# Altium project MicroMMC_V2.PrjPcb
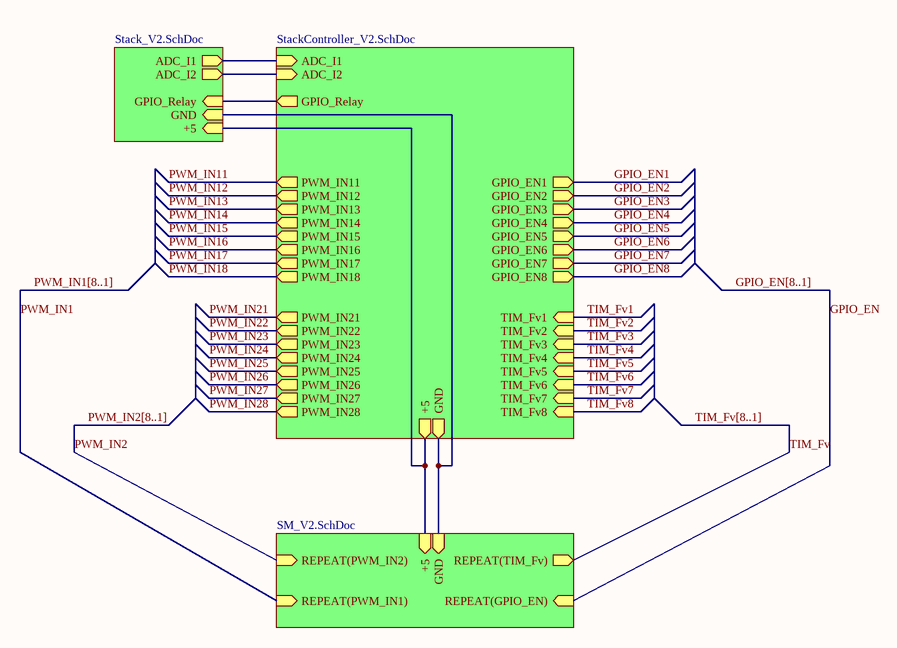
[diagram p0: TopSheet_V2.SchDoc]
4 sheets, 302 parts. Net scope: hierarchical (ports join the sheet entries above them; power ports are global).
Board file: MicroMMC_V2.PcbDoc
Sheets:
  TopSheet_V2.SchDoc
     = Stack_V2.SchDoc
     = StackController_V2.SchDoc
    1 = SM_V2.SchDoc
    2 = SM_V2.SchDoc
    3 = SM_V2.SchDoc
    4 = SM_V2.SchDoc
    5 = SM_V2.SchDoc
    6 = SM_V2.SchDoc
    7 = SM_V2.SchDoc
    8 = SM_V2.SchDoc

## Sheet TopSheet_V2.SchDoc
size A4

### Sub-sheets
REPEAT(,1,8) = SM_V2.SchDoc: REPEAT(PWM_IN1) (in), REPEAT(PWM_IN2) (in), REPEAT(GPIO_EN) (in), REPEAT(TIM_Fv) (out), GND (in), +5 (in)
? = Stack_V2.SchDoc: ADC_I1 (out), ADC_I2 (out), GPIO_Relay (in), GND (in), +5 (in)
? = StackController_V2.SchDoc: ADC_I1 (in), GPIO_Relay (out), PWM_IN11 (out), PWM_IN21 (out), GPIO_EN1 (out), ADC_I2 (in), TIM_Fv1 (in), GPIO_EN2 (out), GPIO_EN3 (out), GPIO_EN4 (out), GPIO_EN5 (out), GPIO_EN6 (out), GPIO_EN7 (out), GPIO_EN8 (out), TIM_Fv2 (in), TIM_Fv3 (in), TIM_Fv4 (in), TIM_Fv5 (in), TIM_Fv6 (in), TIM_Fv7 (in), TIM_Fv8 (in), PWM_IN12 (out), PWM_IN13 (out), PWM_IN14 (out), PWM_IN15 (out), PWM_IN16 (out), PWM_IN17 (out), PWM_IN18 (out), PWM_IN22 (out), PWM_IN23 (out), PWM_IN24 (out), PWM_IN25 (out), PWM_IN26 (out), PWM_IN27 (out), PWM_IN28 (out), +5 (out), GND (out)

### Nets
+5: sheet /+5, sheet /+5, sheet REPEAT(,1,8)/+5
GND: sheet /GND, sheet /GND, sheet REPEAT(,1,8)/GND
ADC_I1: sheet /ADC_I1, sheet /ADC_I1
ADC_I2: sheet /ADC_I2, sheet /ADC_I2
GPIO_Relay: sheet /GPIO_Relay, sheet /GPIO_Relay

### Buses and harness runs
bus GPIO_EN[8..1]
bus PWM_IN1[8..1]
bus PWM_IN2[8..1]
bus TIM_Fv[8..1]

## Sheet Stack_V2.SchDoc
size A4
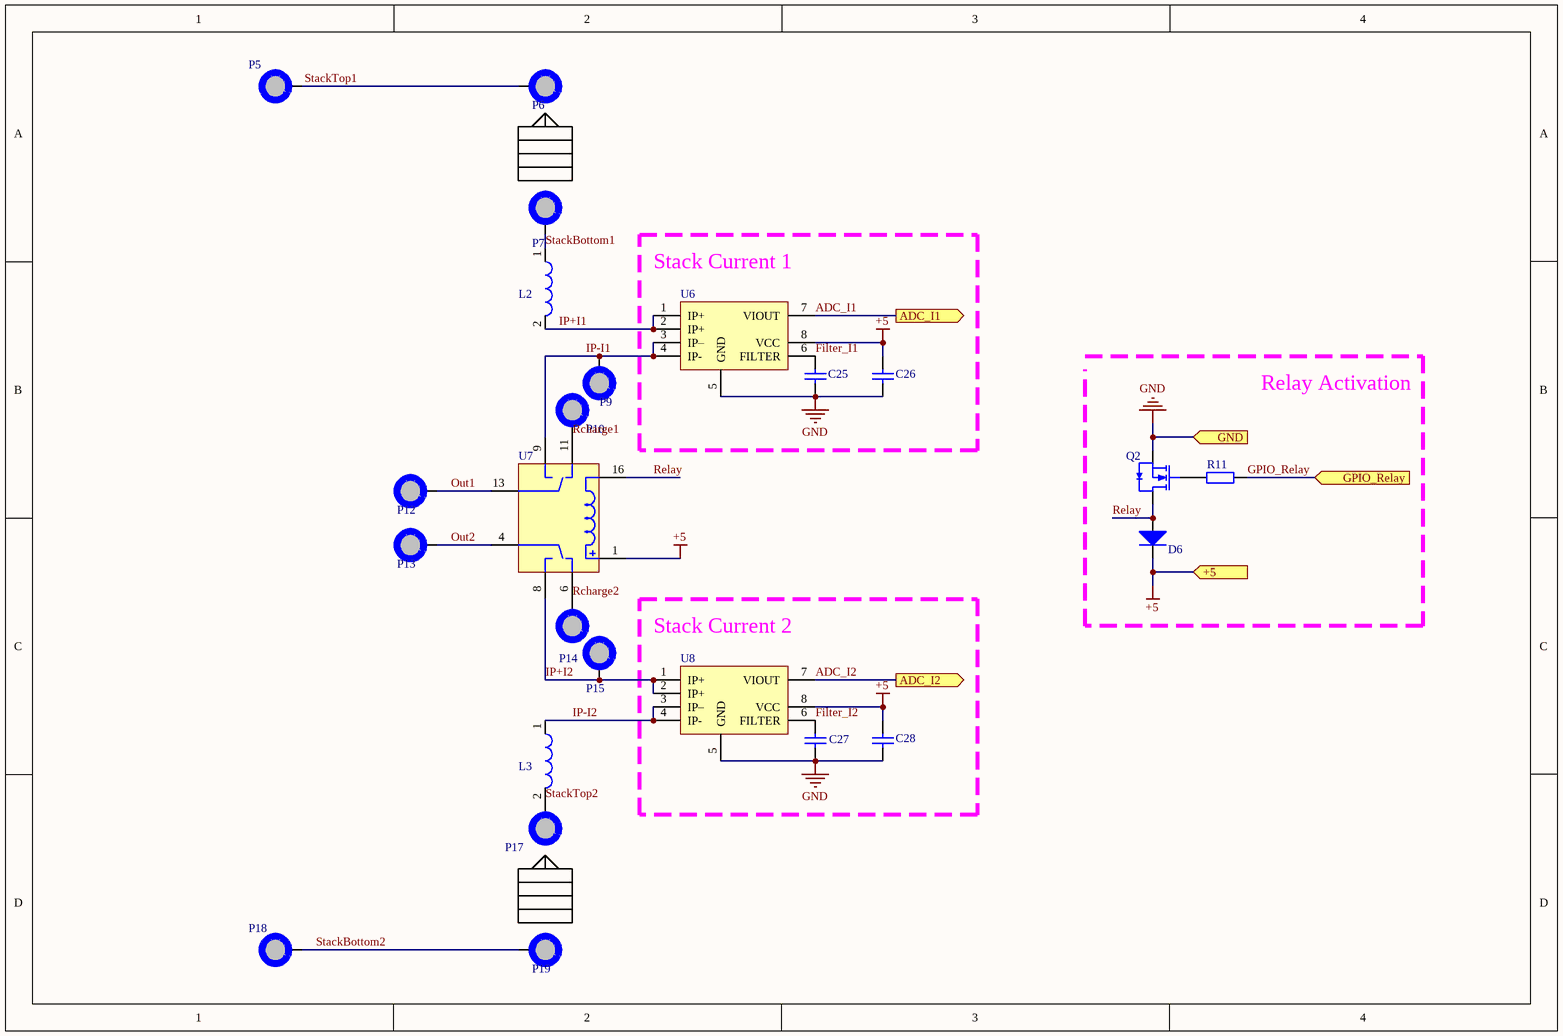
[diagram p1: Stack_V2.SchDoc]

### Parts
C25  1nF (102) ±10% 50V X7R  [0402_C]  (value not drawn)
C26  100nF (104) ±10% 16V X7R  [0402_C]  (value not drawn)
C27  1nF (102) ±10% 50V X7R  [0402_C]  (value not drawn)
C28  100nF (104) ±10% 16V X7R  [0402_C]  (value not drawn)
D6  B5819W  [SOD-123]  (value not drawn)
L2  1140-122K-RC  [INDRD2921W163D3810H2616P]  (value not drawn)
L3  1140-122K-RC  [INDRD2921W163D3810H2616P]  (value not drawn)
P5  4MMx1MM5  [Pad with hole]  (value not drawn)
P6  4MMx1MM5  [Pad with hole]  (value not drawn)
P7  4MMx1MM5  [Pad with hole]  (value not drawn)
P9  4MMx1MM5  [Pad with hole]  (value not drawn)
P10  4MMx1MM5  [Pad with hole]  (value not drawn)
P12  4MMx1MM5  [Pad with hole]  (value not drawn)
P13  4MMx1MM5  [Pad with hole]  (value not drawn)
P14  4MMx1MM5  [Pad with hole]  (value not drawn)
P15  4MMx1MM5  [Pad with hole]  (value not drawn)
P17  4MMx1MM5  [Pad with hole]  (value not drawn)
P18  4MMx1MM5  [Pad with hole]  (value not drawn)
P19  4MMx1MM5  [Pad with hole]  (value not drawn)
Q2  2N7002  [SOT-23(SOT-23-3)]  (value not drawn)
R11  1KΩ (1001) ±1%  [0402_R]  (value not drawn)
U6  ACS712ELCTR-05B-T  [SOIC-8_150mil]  (value not drawn)
U7  V23105A5001A201  [Relay_V23105A5001A201]  (value not drawn)
U8  ACS712ELCTR-05B-T  [SOIC-8_150mil]  (value not drawn)

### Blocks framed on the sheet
Stack Current 1: C25 C26 U6
Stack Current 2: C27 C28 U8

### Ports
+5 (in), ADC_I1 (out), ADC_I2 (out), GND (in), GPIO_Relay (in)

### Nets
+5: C26.2 C28.2 D6.2(K) U6.8(VCC) U7.1 U8.8(VCC) ; port +5
GND: C25.1 C26.1 C27.1 C28.1 Q2.2(S) U6.5(GND) U8.5(GND) ; port GND
ADC_I1: U6.7(VIOUT) ; port ADC_I1
ADC_I2: U8.7(VIOUT) ; port ADC_I2
Filter_I1: C25.2 U6.6(FILTER)
Filter_I2: C27.2 U8.6(FILTER)
GPIO_Relay: R11.1 ; port GPIO_Relay
IP+I1: L2.2 U6.1(IP+) U6.2(IP+)
IP+I2: P15.1 U7.8 U8.1(IP+) U8.2(IP+)
IP-I1: P9.1 U6.3(IP–) U6.4(IP-) U7.9
IP-I2: L3.1 U8.3(IP–) U8.4(IP-)
Out1: P12.1 U7.13
Out2: P13.1 U7.4
Rcharge1: P10.1 U7.11
Rcharge2: P14.1 U7.6
Relay: D6.1(A) Q2.3(D) U7.16
StackBottom1: L2.1 P7.1
StackBottom2: P18.1 P19.1
StackTop1: P5.1 P6.1
StackTop2: L3.2 P17.1
NetQ2_1: Q2.1(G) R11.2

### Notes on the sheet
- Relay Activation

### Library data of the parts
C25 C27 = 1nF (102) ±10% 50V X7R: C1523 贴片电容 0402
C26 C28 = 100nF (104) ±10% 16V X7R: C1525 贴片电容 0402
D6 = B5819W: C8598 SOD-123
L2 L3 = 1140-122K-RC: C1329703 Radial; MF: Bourns
P5-P7 P9 P10 P12-P15 P17-P19 = PAD_WITH_HOLE_4MMx1MM5
Q2 = 2N7002: C8545 SOT-23-3
R11 = 1KΩ (1001) ±1%: C11702 贴片电阻 0402
U6 U8 = ACS712ELCTR-05B-T: C44471 电流传感器 SOIC-8_3.9X4.9X1.27P
U7 = V23105A5001A201: 3A 5V; Manufacturer: TE Connectivity Axicom; Throw Configuration: DPDT; Coil Resistance: 167R; Coil Current: 29.76mA; Max Voltage Rating (AC): 250V; Max Voltage Rating (DC): 220V; Coil Type: Non-Latching; Coil Power: 150mW; Relay Type: Relay; Actuating System: AC/DC; Insertion Loss: -0.27dB; Ratings: IP67; Approvals: cULus

## Sheet StackController_V2.SchDoc
size A3
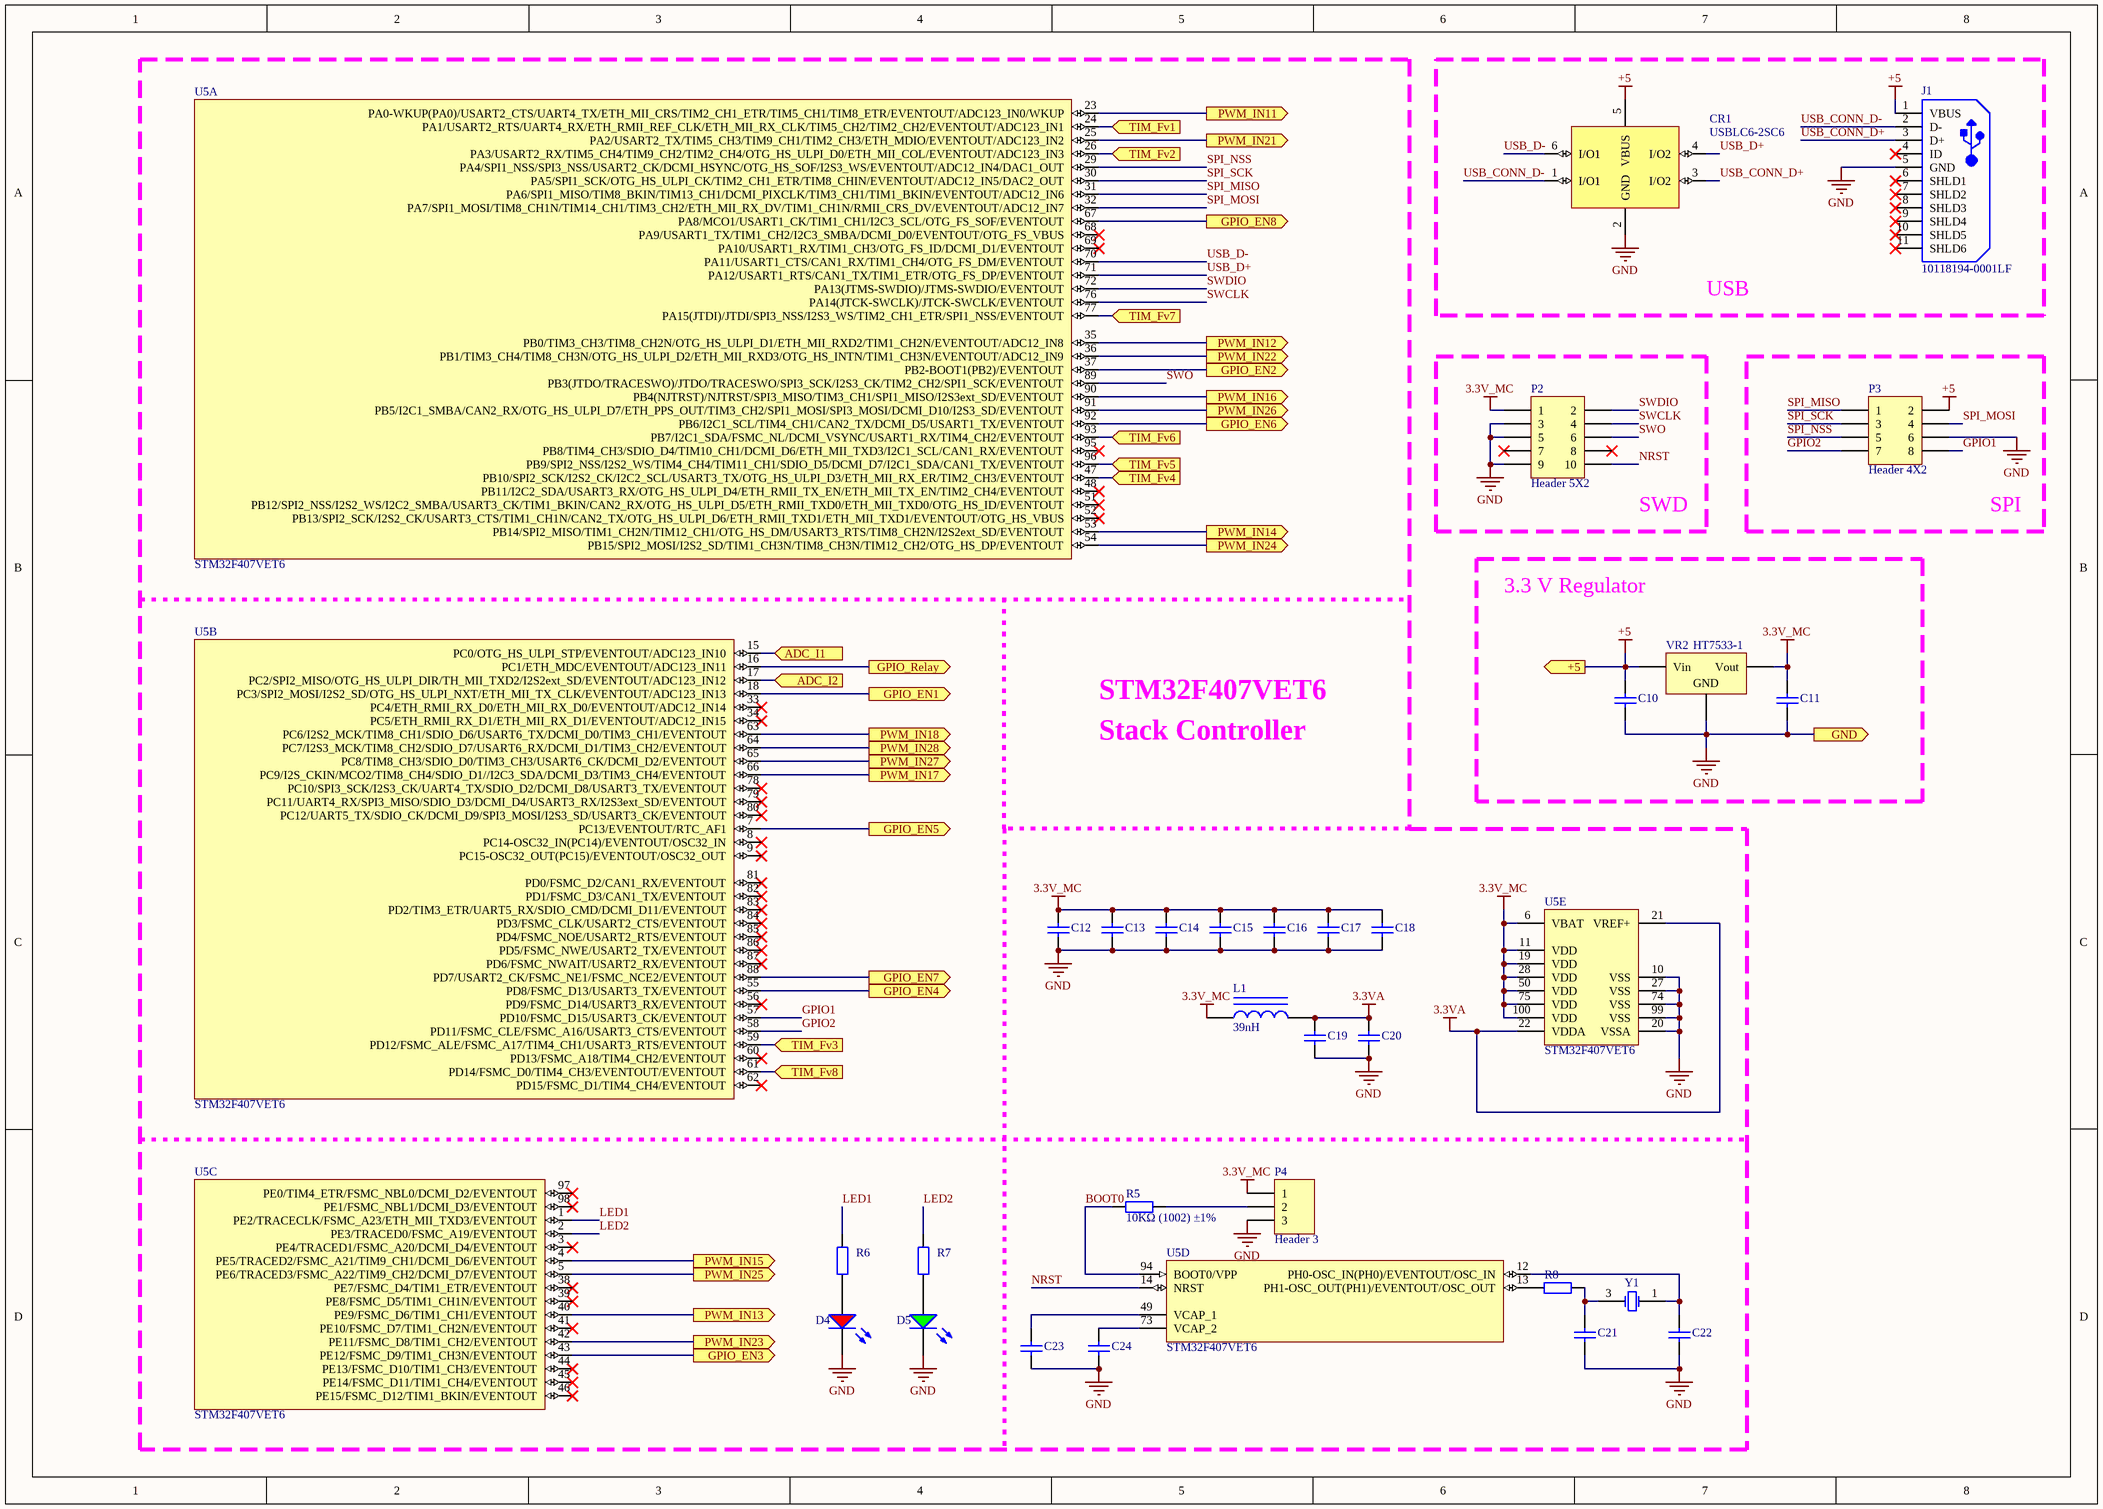
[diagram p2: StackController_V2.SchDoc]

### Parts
C10  10uF (106) ±20% 6.3V X5R  [0402_C]  (value not drawn)
C11  10uF (106) ±20% 6.3V X5R  [0402_C]  (value not drawn)
C12  4.7uF (475) ±20% 10V X5R  [0402_C]  (value not drawn)
C13  100nF (104) ±10% 16V X7R  [0402_C]  (value not drawn)
C14  100nF (104) ±10% 16V X7R  [0402_C]  (value not drawn)
C15  100nF (104) ±10% 16V X7R  [0402_C]  (value not drawn)
C16  100nF (104) ±10% 16V X7R  [0402_C]  (value not drawn)
C17  100nF (104) ±10% 16V X7R  [0402_C]  (value not drawn)
C18  100nF (104) ±10% 16V X7R  [0402_C]  (value not drawn)
C19  1uF (105) ±10% 25V X5R  [0402_C]  (value not drawn)
C20  100nF (104) ±10% 16V X7R  [0402_C]  (value not drawn)
C21  12pF (120) ±5% 50V C0G  [0402_C]  (value not drawn)
C22  12pF (120) ±5% 50V C0G  [0402_C]  (value not drawn)
C23  2.2uF (225) ±10% 16V X5R  [0603_C]  (value not drawn)
C24  2.2uF (225) ±10% 16V X5R  [0603_C]  (value not drawn)
CR1  USBLC6-2SC6  [SOT23-6L_STM]
D4  LED_灯_红_Iv=100-120_λd=615-630  [0603_LED_S1]  (value not drawn)
D5  LED_灯_绿_Iv=112-285_λd=520-535  [0603_LED_S1]  (value not drawn)
J1  10118194-0001LF  [FCI-10118194-0001LF-5_V]
L1  39nH  [0402_L]
P2  Header 5X2  [HDR2.54-LI-2x5P]
P3  Header 4X2  [HDR2.54-LI-2x4P]
P4  Header 3  [HDR2.54-LI-3P]
R5  10KΩ (1002) ±1%  [0402_R]
R6  2.4KΩ (2401) ±1%  [0402_R]  (value not drawn)
R7  2.4KΩ (2401) ±1%  [0402_R]  (value not drawn)
R8  47Ω (47R0) ±1%  [0402_R]  (value not drawn)
U5  STM32F407VET6  [LQFP-100_14x14x05P]  (parts A,B,C,D,E of 5)
VR2  HT7533-1  [SOT-89(SOT-89-3)]
Y1  16MHZ 9PF 10PPM  [SMD-3225_4P]  (value not drawn)

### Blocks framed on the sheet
USB: CR1 J1
SWD: P2
SPI: P3
3.3 V Regulator: C10 C11 VR2

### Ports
+5 (out), ADC_I1 (in), ADC_I2 (in), GND (out), GPIO_EN1 (out), GPIO_EN2 (out), GPIO_EN3 (out), GPIO_EN4 (out), GPIO_EN5 (out), GPIO_EN6 (out), GPIO_EN7 (out), GPIO_EN8 (out), GPIO_Relay (out), PWM_IN11 (out), PWM_IN12 (out), PWM_IN13 (out), PWM_IN14 (out), PWM_IN15 (out), PWM_IN16 (out), PWM_IN17 (out), PWM_IN18 (out), PWM_IN21 (out), PWM_IN22 (out), PWM_IN23 (out), PWM_IN24 (out), PWM_IN25 (out), PWM_IN26 (out), PWM_IN27 (out), PWM_IN28 (out), TIM_Fv1 (in), TIM_Fv2 (in), TIM_Fv3 (in), TIM_Fv4 (in), TIM_Fv5 (in), TIM_Fv6 (in), TIM_Fv7 (in), TIM_Fv8 (in)

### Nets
3.3V_MC: C11.2 C12.2 C13.2 C14.2 C15.2 C16.2 C17.2 C18.2 L1.1 P2.1 P4.1 U5.6(VBAT) U5.11(VDD) U5.19(VDD) U5.28(VDD) U5.50(VDD) U5.75(VDD) U5.100(VDD) VR2.3(Vout)
3.3VA: C19.1 C20.2 L1.2 U5.21(VREF+) U5.22(VDDA)
+5: C10.2 CR1.5(VBUS) J1.1(VBUS) P3.2 VR2.2(Vin) ; port +5
GND: C10.1 C11.1 C12.1 C13.1 C14.1 C15.1 C16.1 C17.1 C18.1 C19.2 C20.1 C21.1 C22.1 C23.1 C24.1 CR1.2(GND) D4.K D5.K J1.5(GND) P2.3 P2.5 P2.9 P3.6 P4.3 U5.10(VSS) U5.20(VSSA) U5.27(VSS) U5.74(VSS) U5.99(VSS) VR2.1(GND) ; port GND
ADC_I1: U5.15(PC0/OTG_HS_ULPI_STP/EVENTOUT/ADC123_IN10) ; port ADC_I1
ADC_I2: U5.17(PC2/SPI2_MISO/OTG_HS_ULPI_DIR/TH_MII_TXD2/I2S2ext_SD/EVENTOUT/ADC123_IN12) ; port ADC_I2
BOOT0: R5.1 U5.94(BOOT0/VPP)
GPIO1: P3.8 U5.57(PD10/FSMC_D15/USART3_CK/EVENTOUT)
GPIO2: P3.7 U5.58(PD11/FSMC_CLE/FSMC_A16/USART3_CTS/EVENTOUT)
GPIO_EN1: U5.18(PC3/SPI2_MOSI/I2S2_SD/OTG_HS_ULPI_NXT/ETH_MII_TX_CLK/EVENTOUT/ADC123_IN13) ; port GPIO_EN1
GPIO_EN2: U5.37(PB2-BOOT1(PB2)/EVENTOUT) ; port GPIO_EN2
GPIO_EN3: U5.43(PE12/FSMC_D9/TIM1_CH3N/EVENTOUT) ; port GPIO_EN3
GPIO_EN4: U5.55(PD8/FSMC_D13/USART3_TX/EVENTOUT) ; port GPIO_EN4
GPIO_EN5: U5.7(PC13/EVENTOUT/RTC_AF1) ; port GPIO_EN5
GPIO_EN6: U5.92(PB6/I2C1_SCL/TIM4_CH1/CAN2_TX/DCMI_D5/USART1_TX/EVENTOUT) ; port GPIO_EN6
GPIO_EN7: U5.88(PD7/USART2_CK/FSMC_NE1/FSMC_NCE2/EVENTOUT) ; port GPIO_EN7
GPIO_EN8: U5.67(PA8/MCO1/USART1_CK/TIM1_CH1/I2C3_SCL/OTG_FS_SOF/EVENTOUT) ; port GPIO_EN8
GPIO_Relay: U5.16(PC1/ETH_MDC/EVENTOUT/ADC123_IN11) ; port GPIO_Relay
LED1: R6.2 U5.1(PE2/TRACECLK/FSMC_A23/ETH_MII_TXD3/EVENTOUT)
LED2: R7.2 U5.2(PE3/TRACED0/FSMC_A19/EVENTOUT)
NRST: P2.10 U5.14(NRST)
PWM_IN11: U5.23(PA0-WKUP(PA0)/USART2_CTS/UART4_TX/ETH_MII_CRS/TIM2_CH1_ETR/TIM5_CH1/TIM8_ETR/EVENTOUT/ADC123_IN0/WKUP) ; port PWM_IN11
PWM_IN12: U5.35(PB0/TIM3_CH3/TIM8_CH2N/OTG_HS_ULPI_D1/ETH_MII_RXD2/TIM1_CH2N/EVENTOUT/ADC12_IN8) ; port PWM_IN12
PWM_IN13: U5.40(PE9/FSMC_D6/TIM1_CH1/EVENTOUT) ; port PWM_IN13
PWM_IN14: U5.53(PB14/SPI2_MISO/TIM1_CH2N/TIM12_CH1/OTG_HS_DM/USART3_RTS/TIM8_CH2N/I2S2ext_SD/EVENTOUT) ; port PWM_IN14
PWM_IN15: U5.4(PE5/TRACED2/FSMC_A21/TIM9_CH1/DCMI_D6/EVENTOUT) ; port PWM_IN15
PWM_IN16: U5.90(PB4(NJTRST)/NJTRST/SPI3_MISO/TIM3_CH1/SPI1_MISO/I2S3ext_SD/EVENTOUT) ; port PWM_IN16
PWM_IN17: U5.66(PC9/I2S_CKIN/MCO2/TIM8_CH4/SDIO_D1//I2C3_SDA/DCMI_D3/TIM3_CH4/EVENTOUT) ; port PWM_IN17
PWM_IN18: U5.63(PC6/I2S2_MCK/TIM8_CH1/SDIO_D6/USART6_TX/DCMI_D0/TIM3_CH1/EVENTOUT) ; port PWM_IN18
PWM_IN21: U5.25(PA2/USART2_TX/TIM5_CH3/TIM9_CH1/TIM2_CH3/ETH_MDIO/EVENTOUT/ADC123_IN2) ; port PWM_IN21
PWM_IN22: U5.36(PB1/TIM3_CH4/TIM8_CH3N/OTG_HS_ULPI_D2/ETH_MII_RXD3/OTG_HS_INTN/TIM1_CH3N/EVENTOUT/ADC12_IN9) ; port PWM_IN22
PWM_IN23: U5.42(PE11/FSMC_D8/TIM1_CH2/EVENTOUT) ; port PWM_IN23
PWM_IN24: U5.54(PB15/SPI2_MOSI/I2S2_SD/TIM1_CH3N/TIM8_CH3N/TIM12_CH2/OTG_HS_DP/EVENTOUT) ; port PWM_IN24
PWM_IN25: U5.5(PE6/TRACED3/FSMC_A22/TIM9_CH2/DCMI_D7/EVENTOUT) ; port PWM_IN25
PWM_IN26: U5.91(PB5/I2C1_SMBA/CAN2_RX/OTG_HS_ULPI_D7/ETH_PPS_OUT/TIM3_CH2/SPI1_MOSI/SPI3_MOSI/DCMI_D10/I2S3_SD/EVENTOUT) ; port PWM_IN26
PWM_IN27: U5.65(PC8/TIM8_CH3/SDIO_D0/TIM3_CH3/USART6_CK/DCMI_D2/EVENTOUT) ; port PWM_IN27
PWM_IN28: U5.64(PC7/I2S3_MCK/TIM8_CH2/SDIO_D7/USART6_RX/DCMI_D1/TIM3_CH2/EVENTOUT) ; port PWM_IN28
SPI_MISO: P3.1 U5.31(PA6/SPI1_MISO/TIM8_BKIN/TIM13_CH1/DCMI_PIXCLK/TIM3_CH1/TIM1_BKIN/EVENTOUT/ADC12_IN6)
SPI_MOSI: P3.4 U5.32(PA7/SPI1_MOSI/TIM8_CH1N/TIM14_CH1/TIM3_CH2/ETH_MII_RX_DV/TIM1_CH1N/RMII_CRS_DV/EVENTOUT/ADC12_IN7)
SPI_NSS: P3.5 U5.29(PA4/SPI1_NSS/SPI3_NSS/USART2_CK/DCMI_HSYNC/OTG_HS_SOF/I2S3_WS/EVENTOUT/ADC12_IN4/DAC1_OUT)
SPI_SCK: P3.3 U5.30(PA5/SPI1_SCK/OTG_HS_ULPI_CK/TIM2_CH1_ETR/TIM8_CHIN/EVENTOUT/ADC12_IN5/DAC2_OUT)
SWCLK: P2.4 U5.76(PA14(JTCK-SWCLK)/JTCK-SWCLK/EVENTOUT)
SWDIO: P2.2 U5.72(PA13(JTMS-SWDIO)/JTMS-SWDIO/EVENTOUT)
SWO: P2.6 U5.89(PB3(JTDO/TRACESWO)/JTDO/TRACESWO/SPI3_SCK/I2S3_CK/TIM2_CH2/SPI1_SCK/EVENTOUT)
TIM_Fv1: U5.24(PA1/USART2_RTS/UART4_RX/ETH_RMII_REF_CLK/ETH_MII_RX_CLK/TIM5_CH2/TIM2_CH2/EVENTOUT/ADC123_IN1) ; port TIM_Fv1
TIM_Fv2: U5.26(PA3/USART2_RX/TIM5_CH4/TIM9_CH2/TIM2_CH4/OTG_HS_ULPI_D0/ETH_MII_COL/EVENTOUT/ADC123_IN3) ; port TIM_Fv2
TIM_Fv3: U5.59(PD12/FSMC_ALE/FSMC_A17/TIM4_CH1/USART3_RTS/EVENTOUT) ; port TIM_Fv3
TIM_Fv4: U5.47(PB10/SPI2_SCK/I2S2_CK/I2C2_SCL/USART3_TX/OTG_HS_ULPI_D3/ETH_MII_RX_ER/TIM2_CH3/EVENTOUT) ; port TIM_Fv4
TIM_Fv5: U5.96(PB9/SPI2_NSS/I2S2_WS/TIM4_CH4/TIM11_CH1/SDIO_D5/DCMI_D7/I2C1_SDA/CAN1_TX/EVENTOUT) ; port TIM_Fv5
TIM_Fv6: U5.93(PB7/I2C1_SDA/FSMC_NL/DCMI_VSYNC/USART1_RX/TIM4_CH2/EVENTOUT) ; port TIM_Fv6
TIM_Fv7: U5.77(PA15(JTDI)/JTDI/SPI3_NSS/I2S3_WS/TIM2_CH1_ETR/SPI1_NSS/EVENTOUT) ; port TIM_Fv7
TIM_Fv8: U5.61(PD14/FSMC_D0/TIM4_CH3/EVENTOUT/EVENTOUT) ; port TIM_Fv8
USB_CONN_D+: CR1.3(I/O2) J1.3(D+)
USB_CONN_D-: CR1.1(I/O1) J1.2(D-)
USB_D+: CR1.4(I/O2) U5.71(PA12/USART1_RTS/CAN1_TX/TIM1_ETR/OTG_FS_DP/EVENTOUT)
USB_D-: CR1.6(I/O1) U5.70(PA11/USART1_CTS/CAN1_RX/TIM1_CH4/OTG_FS_DM/EVENTOUT)
NetC21_2: C21.2 R8.2 Y1.3(OSC2)
NetC22_2: C22.2 U5.12(PH0-OSC_IN(PH0)/EVENTOUT/OSC_IN) Y1.1(OSC1)
NetC23_2: C23.2 U5.49(VCAP_1)
NetC24_2: C24.2 U5.73(VCAP_2)
NetD4_A: D4.A R6.1
NetD5_A: D5.A R7.1
NetP4_2: P4.2 R5.2
NetR8_1: R8.1 U5.13(PH1-OSC_OUT(PH1)/EVENTOUT/OSC_OUT)

Not connected (* = marked no-connect by the designer): J1 4(ID)* 6(SHLD1)* 7(SHLD2)* 8(SHLD3)* 9(SHLD4)* 10(SHLD5)* 11(SHLD6)*; P2 7* 8*; U5 3(PE4/TRACED1/FSMC_A20/DCMI_D4/EVENTOUT)* 8(PC14-OSC32_IN(PC14)/EVENTOUT/OSC32_IN)* 9(PC15-OSC32_OUT(PC15)/EVENTOUT/OSC32_OUT)* 33(PC4/ETH_RMII_RX_D0/ETH_MII_RX_D0/EVENTOUT/ADC12_IN14)* 34(PC5/ETH_RMII_RX_D1/ETH_MII_RX_D1/EVENTOUT/ADC12_IN15)* 38(PE7/FSMC_D4/TIM1_ETR/EVENTOUT)* 39(PE8/FSMC_D5/TIM1_CH1N/EVENTOUT)* 41(PE10/FSMC_D7/TIM1_CH2N/EVENTOUT)* 44(PE13/FSMC_D10/TIM1_CH3/EVENTOUT)* 45(PE14/FSMC_D11/TIM1_CH4/EVENTOUT)* 46(PE15/FSMC_D12/TIM1_BKIN/EVENTOUT)* 48(PB11/I2C2_SDA/USART3_RX/OTG_HS_ULPI_D4/ETH_RMII_TX_EN/ETH_MII_TX_EN/TIM2_CH4/EVENTOUT)* 51(PB12/SPI2_NSS/I2S2_WS/I2C2_SMBA/USART3_CK/TIM1_BKIN/CAN2_RX/OTG_HS_ULPI_D5/ETH_RMII_TXD0/ETH_MII_TXD0/OTG_HS_ID/EVENTOUT)* 52(PB13/SPI2_SCK/I2S2_CK/USART3_CTS/TIM1_CH1N/CAN2_TX/OTG_HS_ULPI_D6/ETH_RMII_TXD1/ETH_MII_TXD1/EVENTOUT/OTG_HS_VBUS)* 56(PD9/FSMC_D14/USART3_RX/EVENTOUT)* 60(PD13/FSMC_A18/TIM4_CH2/EVENTOUT)* 62(PD15/FSMC_D1/TIM4_CH4/EVENTOUT)* 68(PA9/USART1_TX/TIM1_CH2/I2C3_SMBA/DCMI_D0/EVENTOUT/OTG_FS_VBUS)* 69(PA10/USART1_RX/TIM1_CH3/OTG_FS_ID/DCMI_D1/EVENTOUT)* 78(PC10/SPI3_SCK/I2S3_CK/UART4_TX/SDIO_D2/DCMI_D8/USART3_TX/EVENTOUT)* 79(PC11/UART4_RX/SPI3_MISO/SDIO_D3/DCMI_D4/USART3_RX/I2S3ext_SD/EVENTOUT)* 80(PC12/UART5_TX/SDIO_CK/DCMI_D9/SPI3_MOSI/I2S3_SD/USART3_CK/EVENTOUT)* 81(PD0/FSMC_D2/CAN1_RX/EVENTOUT)* 82(PD1/FSMC_D3/CAN1_TX/EVENTOUT)* 83(PD2/TIM3_ETR/UART5_RX/SDIO_CMD/DCMI_D11/EVENTOUT)* 84(PD3/FSMC_CLK/USART2_CTS/EVENTOUT)* 85(PD4/FSMC_NOE/USART2_RTS/EVENTOUT)* 86(PD5/FSMC_NWE/USART2_TX/EVENTOUT)* 87(PD6/FSMC_NWAIT/USART2_RX/EVENTOUT)* 95(PB8/TIM4_CH3/SDIO_D4/TIM10_CH1/DCMI_D6/ETH_MII_TXD3/I2C1_SCL/CAN1_RX/EVENTOUT)* 97(PE0/TIM4_ETR/FSMC_NBL0/DCMI_D2/EVENTOUT)* 98(PE1/FSMC_NBL1/DCMI_D3/EVENTOUT)*

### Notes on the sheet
- STM32F407VET6
- Stack Controller

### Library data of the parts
C10 C11 = 10uF (106) ±20% 6.3V X5R: C15525 贴片电容 0402
C12 = 4.7uF (475) ±20% 10V X5R: C23733 贴片电容 0402
C13-C18 C20 = 100nF (104) ±10% 16V X7R: C1525 贴片电容 0402
C19 = 1uF (105) ±10% 25V X5R: C52923 贴片电容 0402
C21 C22 = 12pF (120) ±5% 50V C0G: C1547 贴片电容 0402
C23 C24 = 2.2uF (225) ±10% 16V X5R: C23630 贴片电容 0603
CR1 = USBLC6-2SC6: C7519 SOT-23-6L; Built_By: EMA_UL_Team; Vendor: STMicroelectronics; SourceLibrary: Update_database_2020-10-15; Type: DEV
D4 = LED_灯_红_Iv=100-120_λd=615-630: C2286 发光二极管 LED_0603
D5 = LED_灯_绿_Iv=112-285_λd=520-535: C72043 发光二极管 LED_0603
J1 = 10118194-0001LF: C132563; Manufacturer: Amphenol FCI; Body Orientation: RightAngle; Number of Contacts: 5; Pitch: 0.65mm; Gender: RCP; Rad Hard: No
L1 = 39nH: C26443 贴片电感 0402
P2 = Header 5X2: C124387
P3 = Header 4X2: C124386
P4 = Header 3: C124376
R5 = 10KΩ (1002) ±1%: C25744 贴片电阻 0402
R6 R7 = 2.4KΩ (2401) ±1%: C25882 贴片电阻 0402
R8 = 47Ω (47R0) ±1%: C25118 贴片电阻 0402
U5 = STM32F407VET6: C28730 ARM
VR2 = HT7533-1: C14289 低压差线性稳压(LDO) SOT-89
Y1 = 16MHZ 9PF 10PPM: C13738 贴片晶振

## Sheet SM_V2.SchDoc
size A4
Used 8 times, as channels 1, 2, 3, 4, 5, 6, 7, 8. Parts and nets are listed once, with the designators drawn on the sheet.
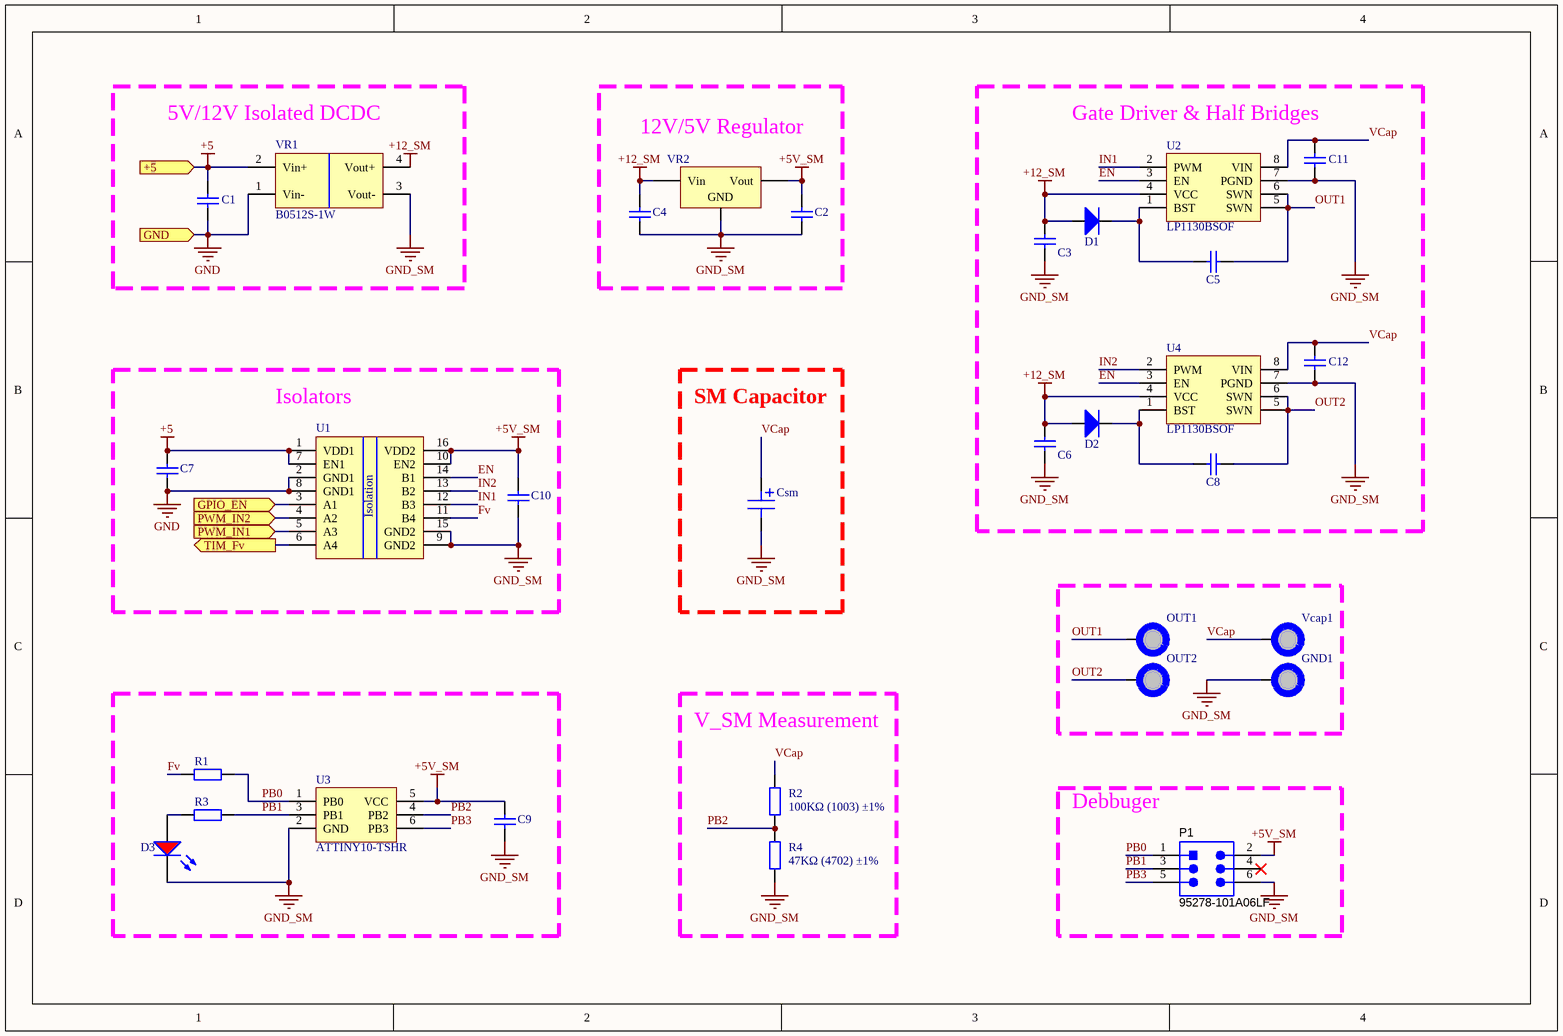
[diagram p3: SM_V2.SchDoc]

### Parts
C1  10uF (106) ±20% 6.3V X5R  [0402_C]  (value not drawn)
C2  10uF (106) ±20% 6.3V X5R  [0402_C]  (value not drawn)
C3  1uF (105) ±10% 25V X5R  [0402_C]  (value not drawn)
C4  10uF 16V  [0603_C]  (value not drawn)
C5  1uF (105) ±10% 25V X5R  [0402_C]  (value not drawn)
C6  1uF (105) ±10% 25V X5R  [0402_C]  (value not drawn)
C7  100nF (104) ±10% 16V X7R  [0402_C]  (value not drawn)
C8  1uF (105) ±10% 25V X5R  [0402_C]  (value not drawn)
C9  100nF (104) ±10% 16V X7R  [0402_C]  (value not drawn)
C10  100nF (104) ±10% 16V X7R  [0402_C]  (value not drawn)
C11  1uF (105) ±10% 25V X5R  [0402_C]  (value not drawn)
C12  1uF (105) ±10% 25V X5R  [0402_C]  (value not drawn)
Csm  6800uF 16V  [6800uF 16V 16*25]  (value not drawn)
D1  B5819W  [SOD-123]  (value not drawn)
D2  B5819W  [SOD-123]  (value not drawn)
D3  LED_灯_红_Iv=100-120_λd=615-630  [0603_LED_S1]  (value not drawn)
GND1  4MMx1MM5  [Pad with hole]  (value not drawn)
OUT1  4MMx1MM5  [Pad with hole]  (value not drawn)
OUT2  4MMx1MM5  [Pad with hole]  (value not drawn)
P1  95278-101A06LF  [AMPM-95278-101A06LF_V]
R1  1KΩ (1001) ±1%  [0402_R]  (value not drawn)
R2  100KΩ (1003) ±1%  [0402_R]
R3  2.4KΩ (2401) ±1%  [0402_R]  (value not drawn)
R4  47KΩ (4702) ±1%  [0402_R]
U1  SI8641BD-B-ISR  [SOIC-16W_SIL]  (value not drawn)
U2  LP1130BSOF  [SOP_8_LP1130B]
U3  ATTINY10-TSHR  [6ST1_ATM]
U4  LP1130BSOF  [SOP_8_LP1130B]
Vcap1  4MMx1MM5  [Pad with hole]  (value not drawn)
VR1  B0512S-1W  [B0512S-1W]
VR2  78L05G-AB3-R  [SOT-89(SOT-89-3)]  (value not drawn)

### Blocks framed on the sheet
5V/12V Isolated DCDC: C1 VR1
12V/5V Regulator: C2 C4 VR2
Gate Driver & Half Bridges: C3 C5 C6 C8 C11 C12 D1 D2 U2 U4
Isolators: C7 C10 U1
SM Capacitor: Csm
V_SM Measurement: R2 R4
Debbuger: P1

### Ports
+5 (in), GND (in), GPIO_EN (in), PWM_IN1 (in), PWM_IN2 (in), TIM_Fv (out)

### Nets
+5: C1.2 C7.2 U1.1(VDD1) U1.7(EN1) VR1.2(Vin+) ; port +5
+5V_SM: C2.2 C9.2 C10.2 P1.2 U1.10(EN2) U1.16(VDD2) U3.5(VCC) VR2.1(Vout)
+12_SM: C3.2 C4.2 C6.2 D1.1(A) D2.1(A) U2.4(VCC) U4.4(VCC) VR1.4(Vout+) VR2.3(Vin)
GND: C1.1 C7.1 U1.2(GND1) U1.8(GND1) VR1.1(Vin-) ; port GND
GND_SM: C2.1 C3.1 C4.1 C6.1 C9.1 C10.1 C11.1 C12.1 Csm.2 D3.K GND1.1 P1.6 R4.1 U1.9(GND2) U1.15(GND2) U2.7(PGND) U3.2(GND) U4.7(PGND) VR1.3(Vout-) VR2.2(GND)
EN: U1.14(B1) U2.3(EN) U4.3(EN)
Fv: R1.1 U1.11(B4)
GPIO_EN: U1.3(A1) ; port GPIO_EN
IN1: U1.12(B3) U2.2(PWM)
IN2: U1.13(B2) U4.2(PWM)
OUT1: C5.2 OUT1.1 U2.5(SWN) U2.6(SWN)
OUT2: C8.2 OUT2.1 U4.5(SWN) U4.6(SWN)
PB0: P1.1 R1.2 U3.1(PB0)
PB1: P1.3 R3.2 U3.3(PB1)
PB2: R2.1 R4.2 U3.4(PB2)
PB3: P1.5 U3.6(PB3)
PWM_IN1: U1.5(A3) ; port PWM_IN1
PWM_IN2: U1.4(A2) ; port PWM_IN2
TIM_Fv: U1.6(A4) ; port TIM_Fv
VCap: C11.2 C12.2 Csm.1 R2.2 U2.8(VIN) U4.8(VIN) Vcap1.1
NetC5_1: C5.1 D1.2(K) U2.1(BST)
NetC8_1: C8.1 D2.2(K) U4.1(BST)
NetD3_A: D3.A R3.1

Not connected (* = marked no-connect by the designer): P1 4*

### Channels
1: designators C1=C1_1 C2=C2_1 C3=C3_1 C4=C4_1 C5=C5_1 C6=C6_1 C7=C7_1 C8=C8_1 C9=C9_1 C10=C10_1 C11=C11_1 C12=C12_1 Csm=Csm_1 D1=D1_1 D2=D2_1 D3=D3_1 GND1=OUT1_1 OUT1=VCap_1 OUT2=GND_SM#1 P1=P1_1 R1=R1_1 R2=R2_1 R3=R3_1 R4=R4_1 U1=U1_1 U2=U2_1 U3=U3_1 U4=U4_1 Vcap1=OUT2_1 VR1=VR1_1 VR2=VR2_1; ports +5=+5 GND=GND GPIO_EN=GPIO_EN1 PWM_IN1=PWM_IN11 PWM_IN2=PWM_IN21 TIM_Fv=TIM_Fv1
2: designators C1=C1_2 C2=C2_2 C3=C3_2 C4=C4_2 C5=C5_2 C6=C6_2 C7=C7_2 C8=C8_2 C9=C9_2 C10=C10_2 C11=C11_2 C12=C12_2 Csm=Csm_2 D1=D1_2 D2=D2_2 D3=D3_2 GND1=OUT1_2 OUT1=VCap_2 OUT2=GND_SM#2 P1=P1_2 R1=R1_2 R2=R2_2 R3=R3_2 R4=R4_2 U1=U1_2 U2=U2_2 U3=U3_2 U4=U4_2 Vcap1=OUT2_2 VR1=VR1_2 VR2=VR2_2; ports +5=+5 GND=GND GPIO_EN=GPIO_EN2 PWM_IN1=PWM_IN12 PWM_IN2=PWM_IN22 TIM_Fv=TIM_Fv2
3: designators C1=C1_3 C2=C2_3 C3=C3_3 C4=C4_3 C5=C5_3 C6=C6_3 C7=C7_3 C8=C8_3 C9=C9_3 C10=C10_3 C11=C11_3 C12=C12_3 Csm=Csm_3 D1=D1_3 D2=D2_3 D3=D3_3 GND1=OUT1_3 OUT1=VCap_3 OUT2=GND_SM#3 P1=P1_3 R1=R1_3 R2=R2_3 R3=R3_3 R4=R4_3 U1=U1_3 U2=U2_3 U3=U3_3 U4=U4_3 Vcap1=OUT2_3 VR1=VR1_3 VR2=VR2_3; ports +5=+5 GND=GND GPIO_EN=GPIO_EN3 PWM_IN1=PWM_IN13 PWM_IN2=PWM_IN23 TIM_Fv=TIM_Fv3
4: designators C1=C1_4 C2=C2_4 C3=C3_4 C4=C4_4 C5=C5_4 C6=C6_4 C7=C7_4 C8=C8_4 C9=C9_4 C10=C10_4 C11=C11_4 C12=C12_4 Csm=Csm_4 D1=D1_4 D2=D2_4 D3=D3_4 GND1=OUT1_4 OUT1=VCap_4 OUT2=GND_SM#4 P1=P1_4 R1=R1_4 R2=R2_4 R3=R3_4 R4=R4_4 U1=U1_4 U2=U2_4 U3=U3_4 U4=U4_4 Vcap1=OUT2_4 VR1=VR1_4 VR2=VR2_4; ports +5=+5 GND=GND GPIO_EN=GPIO_EN4 PWM_IN1=PWM_IN14 PWM_IN2=PWM_IN24 TIM_Fv=TIM_Fv4
5: designators C1=C1_5 C2=C2_5 C3=C3_5 C4=C4_5 C5=C5_5 C6=C6_5 C7=C7_5 C8=C8_5 C9=C9_5 C10=C10_5 C11=C11_5 C12=C12_5 Csm=Csm_5 D1=D1_5 D2=D2_5 D3=D3_5 GND1=OUT1_5 OUT1=VCap_5 OUT2=GND_SM#5 P1=P1_5 R1=R1_5 R2=R2_5 R3=R3_5 R4=R4_5 U1=U1_5 U2=U2_5 U3=U3_5 U4=U4_5 Vcap1=OUT2_5 VR1=VR1_5 VR2=VR2_5; ports +5=+5 GND=GND GPIO_EN=GPIO_EN5 PWM_IN1=PWM_IN15 PWM_IN2=PWM_IN25 TIM_Fv=TIM_Fv5
6: designators C1=C1_6 C2=C2_6 C3=C3_6 C4=C4_6 C5=C5_6 C6=C6_6 C7=C7_6 C8=C8_6 C9=C9_6 C10=C10_6 C11=C11_6 C12=C12_6 Csm=Csm_6 D1=D1_6 D2=D2_6 D3=D3_6 GND1=OUT1_6 OUT1=VCap_6 OUT2=GND_SM#6 P1=P1_6 R1=R1_6 R2=R2_6 R3=R3_6 R4=R4_6 U1=U1_6 U2=U2_6 U3=U3_6 U4=U4_6 Vcap1=OUT2_6 VR1=VR1_6 VR2=VR2_6; ports +5=+5 GND=GND GPIO_EN=GPIO_EN6 PWM_IN1=PWM_IN16 PWM_IN2=PWM_IN26 TIM_Fv=TIM_Fv6
7: designators C1=C1_7 C2=C2_7 C3=C3_7 C4=C4_7 C5=C5_7 C6=C6_7 C7=C7_7 C8=C8_7 C9=C9_7 C10=C10_7 C11=C11_7 C12=C12_7 Csm=Csm_7 D1=D1_7 D2=D2_7 D3=D3_7 GND1=OUT1_7 OUT1=VCap_7 OUT2=GND_SM#7 P1=P1_7 R1=R1_7 R2=R2_7 R3=R3_7 R4=R4_7 U1=U1_7 U2=U2_7 U3=U3_7 U4=U4_7 Vcap1=OUT2_7 VR1=VR1_7 VR2=VR2_7; ports +5=+5 GND=GND GPIO_EN=GPIO_EN7 PWM_IN1=PWM_IN17 PWM_IN2=PWM_IN27 TIM_Fv=TIM_Fv7
8: designators C1=C1_8 C2=C2_8 C3=C3_8 C4=C4_8 C5=C5_8 C6=C6_8 C7=C7_8 C8=C8_8 C9=C9_8 C10=C10_8 C11=C11_8 C12=C12_8 Csm=Csm_8 D1=D1_8 D2=D2_8 D3=D3_8 GND1=OUT1_8 OUT1=VCap_8 OUT2=GND_SM#8 P1=P1_8 R1=R1_8 R2=R2_8 R3=R3_8 R4=R4_8 U1=U1_8 U2=U2_8 U3=U3_8 U4=U4_8 Vcap1=OUT2_8 VR1=VR1_8 VR2=VR2_8; ports +5=+5 GND=GND GPIO_EN=GPIO_EN8 PWM_IN1=PWM_IN18 PWM_IN2=PWM_IN28 TIM_Fv=TIM_Fv8

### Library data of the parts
C1 = 10uF (106) ±20% 6.3V X5R: C15525 6.3V 0402
C2 = 10uF (106) ±20% 6.3V X5R: C15525 贴片电容 0402
C3 C5 C6 C8 C11 C12 = 1uF (105) ±10% 25V X5R: C52923 贴片电容 0402
C4 = 10uF: C92487 10uF 16V 0603
C7 C9 C10 = 100nF (104) ±10% 16V X7R: C1525 贴片电容 0402
Csm = 6800uF 16V: C47893 引线型铝电解电容 Radial,16x25mm; Manufacturer 1: KEMET; Manufacturer Part Number 1: ESK688M010AM2AA
D1 D2 = B5819W: C8598 SOD-123
D3 = LED_灯_红_Iv=100-120_λd=615-630: C2286 发光二极管 LED_0603
GND1 OUT1 OUT2 Vcap1 = PAD_WITH_HOLE_4MMx1MM5
P1 = 95278-101A06LF: C178294; Manufacturer: Amphenol FCI; Power Rating: 100 mW; Tolerance: 1%; Resistance: 49.9 Ohm; Case\Package: 0603; Voltage Rating: 50 V
R1 = 1KΩ (1001) ±1%: C11702 贴片电阻 0402
R2 = 100KΩ (1003) ±1%: C25741 贴片电阻 0402
R3 = 2.4KΩ (2401) ±1%: C25882 贴片电阻 0402
R4 = 47KΩ (4702) ±1%: C25792 贴片电阻 0402
U1 = SI8641BD-B-ISR: C461891 SOIC-16_7.5X10.3X1.27P Extended
U2 U4 = LP1130BSOF: C387697 SOP-8_EP_3.9X4.9X1.27P
U3 = ATTINY10-TSHR: C128438 SOT-23-6L Extended
VR1 = B0512S-1W: Isolated DCDC 0512 C133158
VR2 = 78L05G-AB3-R: C71136 低压差线性稳压(LDO) SOT-89  12-5

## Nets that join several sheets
+5: Stack_V2 (6 pins), StackController_V2 (5 pins), 1 (5 pins), 2 (5 pins), 3 (5 pins), 4 (5 pins), 5 (5 pins), 6 (5 pins), 7 (5 pins), 8 (5 pins)
+5V_SM: 1 (8 pins), 2 (8 pins), 3 (8 pins), 4 (8 pins), 5 (8 pins), 6 (8 pins), 7 (8 pins), 8 (8 pins)
+12_SM: 1 (9 pins), 2 (9 pins), 3 (9 pins), 4 (9 pins), 5 (9 pins), 6 (9 pins), 7 (9 pins), 8 (9 pins)
GND: Stack_V2 (7 pins), StackController_V2 (30 pins), 1 (5 pins), 2 (5 pins), 3 (5 pins), 4 (5 pins), 5 (5 pins), 6 (5 pins), 7 (5 pins), 8 (5 pins)
GND_SM: 1 (20 pins), 2 (20 pins), 3 (20 pins), 4 (20 pins), 5 (20 pins), 6 (20 pins), 7 (20 pins), 8 (20 pins)
ADC_I1: Stack_V2 (U6.7), StackController_V2 (U5.15)
ADC_I2: Stack_V2 (U8.7), StackController_V2 (U5.17)
GPIO_EN1: StackController_V2 (U5.18), 1 (U1_1.3)
GPIO_EN2: StackController_V2 (U5.37), 2 (U1_2.3)
GPIO_EN3: StackController_V2 (U5.43), 3 (U1_3.3)
GPIO_EN4: StackController_V2 (U5.55), 4 (U1_4.3)
GPIO_EN5: StackController_V2 (U5.7), 5 (U1_5.3)
GPIO_EN6: StackController_V2 (U5.92), 6 (U1_6.3)
GPIO_EN7: StackController_V2 (U5.88), 7 (U1_7.3)
GPIO_EN8: StackController_V2 (U5.67), 8 (U1_8.3)
GPIO_Relay: Stack_V2 (R11.1), StackController_V2 (U5.16)
PWM_IN11: StackController_V2 (U5.23), 1 (U1_1.5)
PWM_IN12: StackController_V2 (U5.35), 2 (U1_2.5)
PWM_IN13: StackController_V2 (U5.40), 3 (U1_3.5)
PWM_IN14: StackController_V2 (U5.53), 4 (U1_4.5)
PWM_IN15: StackController_V2 (U5.4), 5 (U1_5.5)
PWM_IN16: StackController_V2 (U5.90), 6 (U1_6.5)
PWM_IN17: StackController_V2 (U5.66), 7 (U1_7.5)
PWM_IN18: StackController_V2 (U5.63), 8 (U1_8.5)
PWM_IN21: StackController_V2 (U5.25), 1 (U1_1.4)
PWM_IN22: StackController_V2 (U5.36), 2 (U1_2.4)
PWM_IN23: StackController_V2 (U5.42), 3 (U1_3.4)
PWM_IN24: StackController_V2 (U5.54), 4 (U1_4.4)
PWM_IN25: StackController_V2 (U5.5), 5 (U1_5.4)
PWM_IN26: StackController_V2 (U5.91), 6 (U1_6.4)
PWM_IN27: StackController_V2 (U5.65), 7 (U1_7.4)
PWM_IN28: StackController_V2 (U5.64), 8 (U1_8.4)
TIM_Fv1: StackController_V2 (U5.24), 1 (U1_1.6)
TIM_Fv2: StackController_V2 (U5.26), 2 (U1_2.6)
TIM_Fv3: StackController_V2 (U5.59), 3 (U1_3.6)
TIM_Fv4: StackController_V2 (U5.47), 4 (U1_4.6)
TIM_Fv5: StackController_V2 (U5.96), 5 (U1_5.6)
TIM_Fv6: StackController_V2 (U5.93), 6 (U1_6.6)
TIM_Fv7: StackController_V2 (U5.77), 7 (U1_7.6)
TIM_Fv8: StackController_V2 (U5.61), 8 (U1_8.6)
